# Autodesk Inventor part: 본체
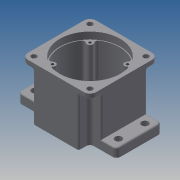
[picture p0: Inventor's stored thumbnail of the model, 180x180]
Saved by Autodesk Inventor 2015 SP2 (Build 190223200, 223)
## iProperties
Created: 2015-06
Part Number: 본체
Material: 일반
Document SubType Name: Modeling
Designer: AMC
Density: 1 g/cm^3
Appearance: 기본값
Author: AMC
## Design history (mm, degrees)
sketch "스케치1"
  geometry: L1 (-45, -45)-(45, -45); L2 (45, -45)-(45, 45); L3 (45, 45)-(-45, 45); L4 (-45, 45)-(-45, -45); L5 (-45, -45)-(45, 45); L6 (45, -45)-(-45, 45); 1 further point
  constraints: 12 end point, 2 midpoint, 2 parallel, 1 horizontal, 1 perpendicular
  dimensions: "d0" = 90 distance of L2.end L3.end; "d1" = 90 distance of L1.end L2.end (= d0)
extrude "돌출1" new body sketch "스케치1" distance "d2" = 7; taper "d3" = 0 deg
fillet "모깎기1" dims "d4" = 8
sketch "스케치2"
  geometry: L1 (45, 37)-(45, -37) reference; L2 (37, -45)-(-37, -45) reference; L3 (-45, -37)-(-45, 37) reference; L4 (-37, 45)-(37, 45) reference; L5 (30, -45)-(-30, -45); L6 (-30, -45)-(-30, -30); L7 (-30, -30)-(-45, -30); L8 (-45, -30)-(-45, 30); L9 (-45, 30)-(-30, 30); L10 (-30, 30)-(-30, 45); L11 (-30, 45)-(30, 45); L12 (30, 45)-(30, 30); L13 (30, 30)-(45, 30); L14 (45, 30)-(45, -30); L15 (45, -30)-(30, -30); L16 (30, -30)-(30, -45); A1 r 8 centre (37, 37) between (45, 37) and (37, 45) reference; A2 r 8 centre (37, -37) between (37, -45) and (45, -37) reference; A3 r 8 centre (-37, -37) between (-45, -37) and (-37, -45) reference; A4 r 8 centre (-37, 37) between (-37, 45) and (-45, 37) reference; 1 further point
  constraints: 24 end point, 10 perpendicular, 2 point on line, 1 horizontal
  dimensions: "d5" = 15 distance between parallel lines of L1 L16; "d6" = 15 distance between parallel lines of L3 L6 (= d5); "d7" = 15 distance between parallel lines of L1 L12 (= d5); "d8" = 0 distance between parallel lines of L2 L5; "d9" = 0 distance between parallel lines of L4 L11; "d10" = 0 distance between parallel lines of L1 L14; "d11" = 0 distance between parallel lines of L3 L8; "d12" = 15 distance between parallel lines of L4 L13 (= d5); "d13" = 15 distance between parallel lines of L2 L15 (= d5); "d14" = 15 distance between parallel lines of L2 L7 (= d6); "d15" = 15 distance between parallel lines of L4 L9 (= d14)
extrude "돌출2" join sketch "스케치2" distance "d16" = 51; taper "d17" = 0 deg
sketch "스케치3"
  geometry: L1 (45, -30)-(30, -30) reference; L2 (30, -30)-(30, -45) reference; L3 (30, -45)-(-30, -45) reference; L4 (-30, -45)-(-30, -30) reference; L5 (-30, -30)-(-45, -30) reference; L6 (-45, -30)-(-45, 30) reference; L7 (-45, 30)-(-30, 30) reference; L8 (-30, 30)-(-30, 45) reference; L9 (-30, 45)-(30, 45) reference; L10 (30, 45)-(30, 30) reference; L11 (30, 30)-(45, 30) reference; L12 (45, 30)-(45, -30) reference; L13 (30, -45)-(30, -30); L14 (30, -30)-(65, -30); L15 (-30, -45)-(30, -45); L16 (-30, -45)-(-30, -30); L17 (-30, -30)-(-65, -30); L18 (-65, -30)-(-65, 30); L19 (-65, 30)-(-30, 30); L20 (-30, 30)-(-30, 45); L21 (-30, 45)-(30, 45); L22 (-37, 45)-(37, 45) reference; L23 (30, 30)-(30, 45); L24 (30, 30)-(65, 30); L25 (65, 30)-(65, -30); 1 further point
  constraints: 24 end point, 5 perpendicular, 4 collinear, 2 horizontal, 1 point on line
  dimensions: "d18" = 35 distance of L1.end L14.end; "d19" = 35 distance of L4.end L17.end
extrude "돌출3" join sketch "스케치3" distance "d20" = 12; taper "d21" = 0 deg
sketch "스케치4"
  geometry: L1 (30, 45)-(30, 30) reference; L2 (30, 30)-(65, 30) reference; L3 (65, 30)-(65, -30) reference; L4 (65, -30)-(30, -30) reference; L5 (30, -30)-(30, -45) reference; L6 (30, -45)-(-30, -45) reference; L7 (-30, -45)-(-30, -30) reference; L8 (-30, -30)-(-65, -30) reference; L9 (-65, -30)-(-65, 30) reference; L10 (-65, 30)-(-30, 30) reference; L11 (-30, 30)-(-30, 45) reference; L12 (-30, 45)-(30, 45) reference; C1 r 25 at (0, -11); 1 further point
  constraints: 1 centre point, 1 vertical alignment
  dimensions: "d22" = 50 diameter of C1; "d23" = 11 distance of point (0, 0) C1.centre
extrude "돌출4" join sketch "스케치4" distance "d24" = 7; taper "d25" = 0 deg
sketch "스케치5"
  geometry: C1 r 40 at (0, 0); 1 further point
  constraints: 1 centre point, 1 coincident
  dimensions: "d26" = 80 diameter of C1
extrude "돌출5" cut sketch "스케치5" distance "d27" = 9; taper "d28" = 0 deg
sketch "스케치6"
  geometry: C1 r 40 at (0, 0) reference; C2 r 39 at (0, 0); 1 further point
  constraints: 1 centre point, 1 coincident
  dimensions: "d29" = 78 diameter of C2
extrude "돌출6" cut sketch "스케치6" distance "d30" = 52; taper "d31" = 0 deg
sketch "스케치7"
  geometry: A1 r 14 centre (0, 20) between (7.402, 8.117) and (-7.402, 8.117); A2 r 20.5 centre (0, -11) between (-7.402, 8.117) and (7.402, 8.117); 1 further point
  constraints: 4 point on circle, 2 centre point, 2 vertical alignment
  dimensions: "d32" = 41 diameter of A2; "d33" = 28 diameter of A1; "d34" = 20 distance of point (0, 0) A1.centre; "d35" = 11 distance of point (0, 0) A2.centre
extrude "돌출7" join sketch "스케치7" distance "d36" = 7; taper "d37" = 0 deg
sketch "스케치8"
  geometry: L1 (14, -63)-(14, -70) reference; L2 (14, -70)-(-36, -70) reference; L3 (-36, -70)-(-36, -63) reference; L4 (-36, -63)-(-45, -63) reference; L5 (-45, -63)-(-45, 7) reference; L6 (-45, 7)-(-40, 7) reference; L7 (-40, 7)-(-40, -2) reference; L8 (-40, -2)-(-39, -2) reference; L9 (-39, -2)-(-39, -54) reference; L10 (-39, -54)-(-31.5, -54) reference; L11 (-31.5, -54)-(-31.5, -47) reference; L12 (-31.5, -47)-(34, -47) reference; L13 (34, -47)-(34, -54) reference; L14 (34, -54)-(39, -54) reference; L15 (39, -54)-(39, -2) reference; L16 (39, -2)-(40, -2) reference; L17 (40, -2)-(40, 7) reference; L18 (40, 7)-(45, 7) reference; L19 (45, 7)-(45, -63) reference; L20 (45, -63)-(14, -63) reference; L21 (-36, -70)-(14, -70) reference; L22 (-27, -70)-(-27, -62); L23 (-27, -62)-(-23.5, -62); L24 (-30, -63)-(30, -63) reference; L25 (-23.5, -62)-(-23.5, -57); L26 (-23.5, -57)-(-28.5, -57); L27 (-28.5, -57)-(-28.5, -47); L28 (8.117, -47)-(-31.5, -47) reference; L29 (-11, -70)-(-11, -47); 1 further point
  constraints: 12 end point, 5 perpendicular, 3 point on line, 1 midpoint, 1 parallel
  dimensions: "d38" = 32 diameter of L22 L29; "d39" = 8 distance of L22.start L22.end; "d40" = 5 distance of L23.end L25.end; "d41" = 25 diameter of L25 L29; "d42" = 35 diameter of L27 L29
revolve "회전1" sketch "스케치8" stored, may be unused: angle "d43" = 90 deg
sketch "스케치9"
  geometry: C1 r 11 at (0, 20); 1 further point
  constraints: 1 centre point
  dimensions: "d44" = 20 distance of point (0, 0) C1.centre; "d45" = 22 diameter of C1
extrude "돌출8" cut sketch "스케치9" distance "d46" = 7; taper "d47" = 0 deg
sketch "스케치10"
  geometry: L1 (-30, 10)-(-30, 25) reference; L2 (-30, 25)-(30, 25) reference; L3 (30, 25)-(30, 10) reference; L4 (30, 10)-(65, 10) reference; L5 (65, 10)-(65, -50) reference; L6 (65, -50)-(30, -50) reference; L7 (30, -50)-(30, -65) reference; L8 (30, -65)-(-30, -65) reference; L9 (-30, -65)-(-30, -50) reference; L10 (-30, -50)-(-65, -50) reference; L11 (-65, -50)-(-65, 10) reference; L12 (-65, 10)-(-30, 10) reference; C1 r 9.5 at (0, 0); C2 r 11 at (0, 0) reference; C3 r 17.5 at (0, -31) reference; C4 r 39 at (0, -20) reference; A1 r 20.5 centre (0, -31) between (-7.402, -11.883) and (7.402, -11.883) reference; A2 r 14 centre (0, 0) between (7.402, -11.883) and (-7.402, -11.883) reference; 1 further point
  constraints: 1 centre point, 1 coincident
  dimensions: "d48" = 19 diameter of C1
extrude "돌출9" cut sketch "스케치10" distance "d49" = 1; taper "d50" = 0 deg
fillet "모깎기2" dims "d51" = 1, "d52" = 0.3
chamfer "모따기1" distance "d53" = 1; stored, may be unused: second distance "d54" = 2, angle "d55" = 45 deg
sketch "스케치11"
  geometry: L1 (30, 30)-(45, 30) reference; L2 (45, 30)-(45, -30) reference; L3 (45, -30)-(30, -30) reference; L4 (30, -30)-(30, -45) reference; L5 (30, -45)-(-30, -45) reference; L6 (-30, -45)-(-30, -30) reference; L7 (-30, -30)-(-45, -30) reference; L8 (-45, -30)-(-45, 30) reference; L9 (-45, 30)-(-30, 30) reference; L10 (-30, 30)-(-30, 45) reference; L11 (-30, 45)-(30, 45) reference; L12 (30, 45)-(30, 30) reference; L13 (21.763, -27.411)-(24.429, -30.401); L14 (27.411, -21.763)-(30.401, -24.429); L15 (0, 0)-(27.393, 0); C1 r 40 at (0, 0) reference; A1 r 39 centre (0, 0) between (24.429, -30.401) and (30.401, -24.429) reference; A2 r 35 centre (0, 0) between (24.749, -24.749) and (21.763, -27.411); A3 r 4 centre (24.749, -24.749) between (21.763, -27.411) and (27.411, -21.763); 1 further point
  constraints: 7 point on circle, 6 end point, 2 centre point, 1 coincident, 1 equal length, 1 horizontal, 1 tangent, 2 other
  dimensions: "d56" = 70 diameter of A2; "d57" = 8 diameter of A3; "d58" = 45 deg dimension on point (0, 0) A2.start L15.end
extrude "돌출10" join sketch "스케치11" stored distance "d59" = 1; taper "d60" = 0 deg
hole "구멍1" diameter "d63" = 3.459; stored, may be unused: countersink angle "d67" = 82 deg, drill point angle "d69" = 118 deg; dims "d61" = 10, "d62" = 10, "d64" = 12, "d65" = 3.023, "d66" = 2, "d68" = 15
sketch "스케치12"
  geometry: L1 (-45, 30)-(-30, 30) reference; L2 (-30, 30)-(-30, 45) reference; L3 (-30, 45)-(30, 45) reference; L4 (30, 45)-(37, 45) reference; L5 (45, 37)-(45, 30) reference; L6 (30, 30)-(45, 30) reference; L7 (30, 45)-(30, 30) reference; L8 (-45, 30)-(-45, 37) reference; L9 (-45, -30)-(-45, 30) reference; L10 (-30, -30)-(-45, -30) reference; L11 (-30, -45)-(-30, -30) reference; L12 (-30, -45)-(-37, -45) reference; L13 (-45, -37)-(-45, -30) reference; L14 (-37, 45)-(-30, 45) reference; L15 (45, 30)-(45, -30) reference; L16 (45, -30)-(45, -37) reference; L17 (37, -45)-(30, -45) reference; L18 (30, -45)-(-30, -45) reference; L19 (45, -30)-(30, -30) reference; L20 (30, -30)-(30, -45) reference; C1 r 40 at (0, 0) reference; A1 r 8 centre (37, 37) between (45, 37) and (37, 45) reference; A2 r 8 centre (-37, -37) between (-45, -37) and (-37, -45) reference; A3 r 8 centre (-37, 37) between (-37, 45) and (-45, 37) reference; A4 r 8 centre (37, -37) between (37, -45) and (45, -37) reference; 1 further point
hole "구멍2" sketch "스케치12" at (-37, -37), (37, -37), (37, 37), (-37, 37) diameter "d73" = 7; stored, may be unused: countersink angle "d77" = 82 deg, drill point angle "d79" = 118 deg; dims "d74" = 8, "d75" = 3.023, "d76" = 2, "d78" = 10.8
fillet "모깎기3" dims "d80" = 3, "d81" = 5, "d98" = 3.5
fillet "모깎기4" dims "d82" = 2
sketch "스케치13"
  geometry: L1 (-65, 25)-(-65, -25) reference; L2 (-43, 30)-(-60, 30) reference; L3 (-60, -30)-(-43, -30) reference; L4 (43, -30)-(60, -30) reference; L5 (65, -25)-(65, 25) reference; L6 (60, 30)-(43, 30) reference; 5 further points
  dimensions: "d83" = 10 distance from line of L1 point (-55, 17.5); "d84" = 12.5 distance from line of L2 point (-55, 17.5); "d85" = 10 distance from line of L1 point (-55, -17.5) (= d83); "d86" = 12.5 distance from line of L3 point (-55, -17.5) (= d84); "d87" = 12.5 distance from line of L4 point (55, -17.5) (= d86); "d88" = 10 distance from line of L5 point (55, -17.5) (= d83); "d89" = 12.5 distance from line of L6 point (55, 17.5) (= d84); "d90" = 10 distance from line of L5 point (55, 17.5)
hole "구멍3" sketch "스케치13" at (-55, 17.5), (-55, -17.5), (55, -17.5), (55, 17.5) diameter "d91" = 9; stored, may be unused: countersink angle "d95" = 82 deg, drill point angle "d97" = 118 deg; dims "d92" = 8, "d93" = 3.023, "d94" = 2, "d96" = 10.8
sketch "스케치14"
  geometry: L1 (28, 45)-(-28, 45) reference; 2 further points
  constraints: 1 vertical alignment, 1 other
  dimensions: "d99" = 15 distance from line of point (0, 30) L1
feature "엠보싱1" sketch "스케치14" dims "d0" = 90, "d1" = 90 (= d0), "d100" = 0.5, "d101" = 0
node "솔리드1"
pattern_circular "원형 패턴1" dims angle "d71" = 360 deg
node "투영된 루프1"
node "절단 모서리 투영1"
node "절단 모서리 투영2"
node "절단 모서리 투영3"
node "절단 모서리 투영4"
node "절단 모서리 투영5"
node "절단 모서리 투영6"
node "절단 모서리 투영7"
